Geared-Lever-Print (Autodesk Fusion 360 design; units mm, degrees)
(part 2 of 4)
sketch "M5 stop reinforcement bolt" plane through (-36.1, 0, 0) normal (1, 0, 0) x axis (0, 0, -1)
  circle C1 centre (-79.6754, -33.9652) radius 2.7
extrude "Extrude12" cut sketch "M5 stop reinforcement bolt" along normal blind 27.2
work_plane "WorkPlane13" AlongDistance -15.4 ExtraOffset 0
sketch "M5 captive stop nut" plane through (-15.4, 0, 0) normal (1, 0, 0) x axis (0, 0, -1)
  line L1 (-83.8754, -31.5403) -> (-79.6754, -29.1154)
  line L2 (-83.8754, -36.39) -> (-83.8754, -31.5403)
  line L3 (-79.6754, -38.8149) -> (-83.8754, -36.39)
  line L4 (-75.4754, -36.39) -> (-79.6754, -38.8149)
  line L5 (-75.4754, -31.5403) -> (-75.4754, -36.39)
  line L6 (-79.6754, -29.1154) -> (-75.4754, -31.5403)
extrude "Extrude13" cut sketch "M5 captive stop nut" along normal blind 6.5
work_plane "WorkPlane14" AlongDistance -36 ExtraOffset 0
sketch "Broad stop support ear (1)" plane through (-36, 0, 0) normal (1, 0, 0) x axis (0, 0, -1)
  line L1 (-60, 44) -> (-60, 20)
  line L2 (-90, 44) -> (-60, 44)
  line L3 (-90, 20) -> (-90, 44)
  line L4 (-60, 20) -> (-90, 20)
extrude "Extrude14" add sketch "Broad stop support ear (1)" along normal blind 12
work_plane "WorkPlane15" AlongDistance -24 ExtraOffset 0
sketch "Integrated steel-core end stop (1)" plane through (-24, 0, 0) normal (1, 0, 0) x axis (0, 0, -1)
  circle C1 centre (-79.6754, 33.9652) radius 6
extrude "Extrude15" add sketch "Integrated steel-core end stop (1)" along normal blind 15
work_plane "WorkPlane16" AlongDistance -36.1 ExtraOffset 0
sketch "M5 stop reinforcement bolt (1)" plane through (-36.1, 0, 0) normal (1, 0, 0) x axis (0, 0, -1)
  circle C1 centre (-79.6754, 33.9652) radius 2.7
extrude "Extrude16" cut sketch "M5 stop reinforcement bolt (1)" along normal blind 27.2
work_plane "WorkPlane17" AlongDistance -15.4 ExtraOffset 0
sketch "M5 captive stop nut (1)" plane through (-15.4, 0, 0) normal (1, 0, 0) x axis (0, 0, -1)
  line L1 (-83.8754, 36.39) -> (-79.6754, 38.8149)
  line L2 (-83.8754, 31.5403) -> (-83.8754, 36.39)
  line L3 (-79.6754, 29.1154) -> (-83.8754, 31.5403)
  line L4 (-75.4754, 31.5403) -> (-79.6754, 29.1154)
  line L5 (-75.4754, 36.39) -> (-75.4754, 31.5403)
  line L6 (-79.6754, 38.8149) -> (-75.4754, 36.39)
extrude "Extrude17" cut sketch "M5 captive stop nut (1)" along normal blind 6.5
work_plane "WorkPlane13" AlongDistance -24 ExtraOffset 0
sketch "Restore shaft socket through stop-lug root" plane through (-24, 0, 0) normal (1, 0, 0) x axis (0, 0, -1)
  line L1 (-69.6247, 6.65) -> (-60.3753, 6.65)
  arc A1 centre (-65, 0) radius 8.1 clockwise from (-60.3753, 6.65) to (-69.6247, 6.65)
extrude "Extrude13" cut sketch "Restore shaft socket through stop-lug root" along normal blind 48
work_plane "WorkPlane10" AlongDistance -24.1 ExtraOffset 0
sketch "Cam sweep clearance through crossblock" plane through (-24.1, 0, 0) normal (1, 0, 0) x axis (0, 0, -1)
  circle C1 centre (-65, 0) radius 51
extrude "Extrude10" cut sketch "Cam sweep clearance through crossblock" along normal blind 48.2
work_plane "WorkPlane10" AlongDistance 36 ExtraOffset 0
sketch "Rigid sensor carriage support" plane through (36, 0, 0) normal (1, 0, 0) x axis (0, 0, -1)
  line L1 (-49, -18) -> (-49, -28)
  line L2 (-81, -18) -> (-49, -18)
  line L3 (-81, -28) -> (-81, -18)
  line L4 (-49, -28) -> (-81, -28)
extrude "Extrude10" add sketch "Rigid sensor carriage support" along normal blind 44
work_plane "WorkPlane11" AlongDistance -28.1 ExtraOffset 0
sketch "M3 sensor carriage heat set" plane through (0, -28.1, 0) normal (0, 1, 0) x axis (1, 0, 0)
  circle C1 centre (74, -65) radius 2
extrude "Extrude11" cut sketch "M3 sensor carriage heat set" along normal blind 6.8
work_plane "WorkPlane12" AlongDistance 36 ExtraOffset 0
sketch "Rigid sensor carriage support (1)" plane through (36, 0, 0) normal (1, 0, 0) x axis (0, 0, -1)
  line L1 (-49, 28) -> (-49, 18)
  line L2 (-81, 28) -> (-49, 28)
  line L3 (-81, 18) -> (-81, 28)
  line L4 (-49, 18) -> (-81, 18)
extrude "Extrude12" add sketch "Rigid sensor carriage support (1)" along normal blind 44
work_plane "WorkPlane13" AlongDistance 21.3 ExtraOffset 0
sketch "M3 sensor carriage heat set (1)" plane through (0, 21.3, 0) normal (0, 1, 0) x axis (1, 0, 0)
  circle C1 centre (74, -65) radius 2
extrude "Extrude13" cut sketch "M3 sensor carriage heat set (1)" along normal blind 6.8
work_plane "WorkPlane1" AlongDistance -24 ExtraOffset 0
sketch "Controlled follower end float" plane through (-24, 0, 0) normal (1, 0, 0) x axis (0, 0, -1)
  circle C1 centre (-12, -35) radius 6
extrude "Extrude1" new body sketch "Controlled follower end float" along normal blind 27.8 bodies "P21 Follower left axial spacer"
work_plane "WorkPlane2" AlongDistance -24.1 ExtraOffset 0
sketch "Pivot sleeve running clearance" plane through (-24.1, 0, 0) normal (1, 0, 0) x axis (0, 0, -1)
  circle C1 centre (-12, -35) radius 4.2
extrude "Extrude2" cut sketch "Pivot sleeve running clearance" along normal blind 28
work_plane "WorkPlane1" AlongDistance 20.2 ExtraOffset 0
sketch "Controlled follower end float" plane through (20.2, 0, 0) normal (1, 0, 0) x axis (0, 0, -1)
  circle C1 centre (-12, -35) radius 6
extrude "Extrude1" new body sketch "Controlled follower end float" along normal blind 3.8 bodies "P22 Follower right axial spacer"
work_plane "WorkPlane2" AlongDistance 20.1 ExtraOffset 0
sketch "Pivot sleeve running clearance" plane through (20.1, 0, 0) normal (1, 0, 0) x axis (0, 0, -1)
  circle C1 centre (-12, -35) radius 4.2
extrude "Extrude2" cut sketch "Pivot sleeve running clearance" along normal blind 4
work_plane "WorkPlane1" AlongDistance 3.1 ExtraOffset 0
sketch "Roller axle M3 nut" plane through (3.1, 0, 0) normal (1, 0, 0) x axis (0, 0, -1)
  line L1 (-14.75, 1.5877) -> (-12, 3.1754)
  line L2 (-14.75, -1.5877) -> (-14.75, 1.5877)
  line L3 (-12, -3.1754) -> (-14.75, -1.5877)
  line L4 (-9.25, -1.5877) -> (-12, -3.1754)
  line L5 (-9.25, 1.5877) -> (-9.25, -1.5877)
  line L6 (-12, 3.1754) -> (-9.25, 1.5877)
extrude "Extrude1" new body sketch "Roller axle M3 nut" along normal blind 2.4 bodies "HARDWARE Roller axle M3 nut"
work_plane "WorkPlane2" AlongDistance 3 ExtraOffset 0
sketch "Thread envelope" plane through (3, 0, 0) normal (1, 0, 0) x axis (0, 0, -1)
  circle C1 centre (-12, 0) radius 1.5
extrude "Extrude2" cut sketch "Thread envelope" along normal blind 2.6
work_plane "WorkPlane14" AlongDistance 23.9 ExtraOffset 0
sketch "Cam lateral service opening" plane through (23.9, 0, 0) normal (1, 0, 0) x axis (0, 0, -1)
  line L1 (-42.2047, 46.7373) -> (-43.8497, 47.5044)
  line L2 (-40.5875, 45.9133) -> (-42.2047, 46.7373)
  line L3 (-39, 45.0333) -> (-40.5875, 45.9133)
  line L4 (-37.4442, 44.0985) -> (-39, 45.0333)
  line L5 (-35.922, 43.11) -> (-37.4442, 44.0985)
  line L6 (-34.4352, 42.0689) -> (-35.922, 43.11)
  line L7 (-32.9856, 40.9766) -> (-34.4352, 42.0689)
  line L8 (-31.575, 39.8343) -> (-32.9856, 40.9766)
  line L9 (-30.2052, 38.6435) -> (-31.575, 39.8343)
  line L10 (-28.8778, 37.4057) -> (-30.2052, 38.6435)
  line L11 (-27.5943, 36.1222) -> (-28.8778, 37.4057)
  line L12 (-26.3565, 34.7948) -> (-27.5943, 36.1222)
  line L13 (-25.1657, 33.425) -> (-26.3565, 34.7948)
  line L14 (-24.0234, 32.0144) -> (-25.1657, 33.425)
  line L15 (-22.9311, 30.5648) -> (-24.0234, 32.0144)
  line L16 (-21.89, 29.078) -> (-22.9311, 30.5648)
  line L17 (-20.9015, 27.5558) -> (-21.89, 29.078)
  line L18 (-19.9667, 26) -> (-20.9015, 27.5558)
  line L19 (-19.0867, 24.4125) -> (-19.9667, 26)
  line L20 (-18.2627, 22.7953) -> (-19.0867, 24.4125)
  line L21 (-17.4956, 21.1503) -> (-18.2627, 22.7953)
  line L22 (-16.7864, 19.4795) -> (-17.4956, 21.1503)
  line L23 (-16.136, 17.785) -> (-16.7864, 19.4795)
  line L24 (-15.5451, 16.0689) -> (-16.136, 17.785)
  line L25 (-15.0144, 14.3331) -> (-15.5451, 16.0689)
  line L26 (-14.5446, 12.5799) -> (-15.0144, 14.3331)
  line L27 (-14.1363, 10.8114) -> (-14.5446, 12.5799)
  line L28 (-13.79, 9.0297) -> (-14.1363, 10.8114)
  line L29 (-13.5061, 7.237) -> (-13.79, 9.0297)
  line L30 (-13.2849, 5.4355) -> (-13.5061, 7.237)
  line L31 (-13.1267, 3.6273) -> (-13.2849, 5.4355)
  line L32 (-13.0317, 1.8148) -> (-13.1267, 3.6273)
  line L33 (-13, 0) -> (-13.0317, 1.8148)
  line L34 (-13.0317, -1.8148) -> (-13, 0)
  line L35 (-13.1267, -3.6273) -> (-13.0317, -1.8148)
  line L36 (-13.2849, -5.4355) -> (-13.1267, -3.6273)
  line L37 (-13.5061, -7.237) -> (-13.2849, -5.4355)
  line L38 (-13.79, -9.0297) -> (-13.5061, -7.237)
  line L39 (-14.1363, -10.8114) -> (-13.79, -9.0297)
  line L40 (-14.5446, -12.5799) -> (-14.1363, -10.8114)
  line L41 (-15.0144, -14.3331) -> (-14.5446, -12.5799)
  line L42 (-15.5451, -16.0689) -> (-15.0144, -14.3331)
  line L43 (-16.136, -17.785) -> (-15.5451, -16.0689)
  line L44 (-16.7864, -19.4795) -> (-16.136, -17.785)
  line L45 (-17.4956, -21.1503) -> (-16.7864, -19.4795)
  line L46 (-18.2627, -22.7953) -> (-17.4956, -21.1503)
  line L47 (-19.0867, -24.4125) -> (-18.2627, -22.7953)
  line L48 (-19.9667, -26) -> (-19.0867, -24.4125)
  line L49 (-20.9015, -27.5558) -> (-19.9667, -26)
  line L50 (-21.89, -29.078) -> (-20.9015, -27.5558)
  line L51 (-22.9311, -30.5648) -> (-21.89, -29.078)
  line L52 (-24.0234, -32.0144) -> (-22.9311, -30.5648)
  line L53 (-25.1657, -33.425) -> (-24.0234, -32.0144)
  line L54 (-26.3565, -34.7948) -> (-25.1657, -33.425)
  line L55 (-27.5943, -36.1222) -> (-26.3565, -34.7948)
  line L56 (-28.8778, -37.4057) -> (-27.5943, -36.1222)
  line L57 (-30.2052, -38.6435) -> (-28.8778, -37.4057)
  line L58 (-31.575, -39.8343) -> (-30.2052, -38.6435)
  line L59 (-32.9856, -40.9766) -> (-31.575, -39.8343)
  line L60 (-34.4352, -42.0689) -> (-32.9856, -40.9766)
  line L61 (-35.922, -43.11) -> (-34.4352, -42.0689)
  line L62 (-37.4442, -44.0985) -> (-35.922, -43.11)
  line L63 (-39, -45.0333) -> (-37.4442, -44.0985)
  line L64 (-40.5875, -45.9133) -> (-39, -45.0333)
  line L65 (-42.2047, -46.7373) -> (-40.5875, -45.9133)
  line L66 (-43.8497, -47.5044) -> (-42.2047, -46.7373)
  line L67 (-54.4248, -23.7522) -> (-43.8497, -47.5044)
  line L68 (-53.6024, -23.3686) -> (-54.4248, -23.7522)
  line L69 (-52.7937, -22.9566) -> (-53.6024, -23.3686)
  line L70 (-52, -22.5167) -> (-52.7937, -22.9566)
  line L71 (-51.2221, -22.0493) -> (-52, -22.5167)
  line L72 (-50.461, -21.555) -> (-51.2221, -22.0493)
  line L73 (-49.7176, -21.0344) -> (-50.461, -21.555)
  line L74 (-48.9928, -20.4883) -> (-49.7176, -21.0344)
  line L75 (-48.2875, -19.9172) -> (-48.9928, -20.4883)
  line L76 (-47.6026, -19.3218) -> (-48.2875, -19.9172)
  line L77 (-46.9389, -18.7028) -> (-47.6026, -19.3218)
  line L78 (-46.2972, -18.0611) -> (-46.9389, -18.7028)
  line L79 (-45.6782, -17.3974) -> (-46.2972, -18.0611)
  line L80 (-45.0828, -16.7125) -> (-45.6782, -17.3974)
  line L81 (-44.5117, -16.0072) -> (-45.0828, -16.7125)
  line L82 (-43.9656, -15.2824) -> (-44.5117, -16.0072)
  line L83 (-43.445, -14.539) -> (-43.9656, -15.2824)
  line L84 (-42.9507, -13.7779) -> (-43.445, -14.539)
  line L85 (-42.4833, -13) -> (-42.9507, -13.7779)
  line L86 (-42.0434, -12.2063) -> (-42.4833, -13)
  line L87 (-41.6314, -11.3976) -> (-42.0434, -12.2063)
  line L88 (-41.2478, -10.5752) -> (-41.6314, -11.3976)
  line L89 (-40.8932, -9.7398) -> (-41.2478, -10.5752)
  line L90 (-40.568, -8.8925) -> (-40.8932, -9.7398)
  line L91 (-40.2725, -8.0344) -> (-40.568, -8.8925)
  line L92 (-40.0072, -7.1666) -> (-40.2725, -8.0344)
  line L93 (-39.7723, -6.29) -> (-40.0072, -7.1666)
  line L94 (-39.5682, -5.4057) -> (-39.7723, -6.29)
  line L95 (-39.395, -4.5149) -> (-39.5682, -5.4057)
  line L96 (-39.253, -3.6185) -> (-39.395, -4.5149)
  line L97 (-39.1424, -2.7177) -> (-39.253, -3.6185)
  line L98 (-39.0633, -1.8137) -> (-39.1424, -2.7177)
  line L99 (-39.0158, -0.9074) -> (-39.0633, -1.8137)
  line L100 (-39, 0) -> (-39.0158, -0.9074)
  line L101 (-39.0158, 0.9074) -> (-39, 0)
  line L102 (-39.0633, 1.8137) -> (-39.0158, 0.9074)
  line L103 (-39.1424, 2.7177) -> (-39.0633, 1.8137)
  line L104 (-39.253, 3.6185) -> (-39.1424, 2.7177)
  line L105 (-39.395, 4.5149) -> (-39.253, 3.6185)
  line L106 (-39.5682, 5.4057) -> (-39.395, 4.5149)
  line L107 (-39.7723, 6.29) -> (-39.5682, 5.4057)
  line L108 (-40.0072, 7.1666) -> (-39.7723, 6.29)
  line L109 (-40.2725, 8.0344) -> (-40.0072, 7.1666)
  line L110 (-40.568, 8.8925) -> (-40.2725, 8.0344)
  line L111 (-40.8932, 9.7398) -> (-40.568, 8.8925)
  line L112 (-41.2478, 10.5752) -> (-40.8932, 9.7398)
  line L113 (-41.6314, 11.3976) -> (-41.2478, 10.5752)
  line L114 (-42.0434, 12.2063) -> (-41.6314, 11.3976)
  line L115 (-42.4833, 13) -> (-42.0434, 12.2063)
  line L116 (-42.9507, 13.7779) -> (-42.4833, 13)
  line L117 (-43.445, 14.539) -> (-42.9507, 13.7779)
  line L118 (-43.9656, 15.2824) -> (-43.445, 14.539)
  line L119 (-44.5117, 16.0072) -> (-43.9656, 15.2824)
  line L120 (-45.0828, 16.7125) -> (-44.5117, 16.0072)
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extrude "Extrude14" cut sketch "Cam lateral service opening" along normal blind 12.2
work_plane "WorkPlane15" AlongDistance 36 ExtraOffset 0
sketch "Clear service path beneath sensor rails" plane through (36, 0, 0) normal (1, 0, 0) x axis (0, 0, -1)
  line L1 (-48.9, -18) -> (-48.9, -28)
  line L2 (-56, -18) -> (-48.9, -18)
  line L3 (-56, -28) -> (-56, -18)
  line L4 (-48.9, -28) -> (-56, -28)
extrude "Extrude15" cut sketch "Clear service path beneath sensor rails" along normal blind 44.1
work_plane "WorkPlane16" AlongDistance 36 ExtraOffset 0
sketch "Clear service path beneath sensor rails (1)" plane through (36, 0, 0) normal (1, 0, 0) x axis (0, 0, -1)
  line L1 (-48.9, 28) -> (-48.9, 18)
  line L2 (-56, 28) -> (-48.9, 28)
  line L3 (-56, 18) -> (-56, 28)
  line L4 (-48.9, 18) -> (-56, 18)
extrude "Extrude16" cut sketch "Clear service path beneath sensor rails (1)" along normal blind 44.1
work_plane "WorkPlane11" AlongDistance -24 ExtraOffset 0
sketch "Raise mount clear of rail bolt axes" plane through (-24, 0, 0) normal (1, 0, 0) x axis (0, 0, -1)
  line L1 (-52, -44) -> (-52, -66)
  line L2 (-57, -44) -> (-52, -44)
  line L3 (-57, -66) -> (-57, -44)
  line L4 (-52, -66) -> (-57, -66)
extrude "Extrude11" add sketch "Raise mount clear of rail bolt axes" along normal blind 48
work_plane "WorkPlane12" AlongDistance -24 ExtraOffset 0
sketch "Close old block mounting hole" plane through (-24, 0, 0) normal (1, 0, 0) x axis (0, 0, -1)
  circle C1 centre (-44, -59) radius 2.01
extrude "Extrude12" add sketch "Close old block mounting hole" along normal blind 8.7
work_plane "WorkPlane13" AlongDistance -24.1 ExtraOffset 0
sketch "Raised M3 block insert" plane through (-24.1, 0, 0) normal (1, 0, 0) x axis (0, 0, -1)
  circle C1 centre (-52, -59) radius 2
extrude "Extrude13" cut sketch "Raised M3 block insert" along normal blind 8.9
work_plane "WorkPlane14" AlongDistance 15.3 ExtraOffset 0
sketch "Close old block mounting hole (1)" plane through (15.3, 0, 0) normal (1, 0, 0) x axis (0, 0, -1)
  circle C1 centre (-44, -59) radius 2.01
extrude "Extrude14" add sketch "Close old block mounting hole (1)" along normal blind 8.7
work_plane "WorkPlane15" AlongDistance 15.2 ExtraOffset 0
sketch "Raised M3 block insert (1)" plane through (15.2, 0, 0) normal (1, 0, 0) x axis (0, 0, -1)
  circle C1 centre (-52, -59) radius 2
extrude "Extrude15" cut sketch "Raised M3 block insert (1)" along normal blind 8.9
work_plane "WorkPlane18" AlongDistance -36 ExtraOffset 0
sketch "Close old plate mounting hole" plane through (-36, 0, 0) normal (1, 0, 0) x axis (0, 0, -1)
  circle C1 centre (-44, -59) radius 1.71
extrude "Extrude18" add sketch "Close old plate mounting hole" along normal blind 12
work_plane "WorkPlane19" AlongDistance -36.1 ExtraOffset 0
sketch "Raised M3 block fastener" plane through (-36.1, 0, 0) normal (1, 0, 0) x axis (0, 0, -1)
  circle C1 centre (-52, -59) radius 1.7
extrude "Extrude19" cut sketch "Raised M3 block fastener" along normal blind 12.2
work_plane "WorkPlane17" AlongDistance 24 ExtraOffset 0
sketch "Close old plate mounting hole" plane through (24, 0, 0) normal (1, 0, 0) x axis (0, 0, -1)
  circle C1 centre (-44, -59) radius 1.71
extrude "Extrude17" add sketch "Close old plate mounting hole" along normal blind 12
work_plane "WorkPlane18" AlongDistance 23.9 ExtraOffset 0
sketch "Raised M3 block fastener" plane through (23.9, 0, 0) normal (1, 0, 0) x axis (0, 0, -1)
  circle C1 centre (-52, -59) radius 1.7
extrude "Extrude18" cut sketch "Raised M3 block fastener" along normal blind 12.2
work_plane "WorkPlane16" AlongDistance -24 ExtraOffset 0
sketch "Close old block mounting hole (2)" plane through (-24, 0, 0) normal (1, 0, 0) x axis (0, 0, -1)
  circle C1 centre (-44, -51) radius 2.01
extrude "Extrude16" add sketch "Close old block mounting hole (2)" along normal blind 8.7
work_plane "WorkPlane17" AlongDistance -24.1 ExtraOffset 0
sketch "Raised M3 block insert (2)" plane through (-24.1, 0, 0) normal (1, 0, 0) x axis (0, 0, -1)
  circle C1 centre (-52, -51) radius 2
extrude "Extrude17" cut sketch "Raised M3 block insert (2)" along normal blind 8.9
work_plane "WorkPlane18" AlongDistance 15.3 ExtraOffset 0
sketch "Close old block mounting hole (3)" plane through (15.3, 0, 0) normal (1, 0, 0) x axis (0, 0, -1)
  circle C1 centre (-44, -51) radius 2.01
extrude "Extrude18" add sketch "Close old block mounting hole (3)" along normal blind 8.7
work_plane "WorkPlane19" AlongDistance 15.2 ExtraOffset 0
sketch "Raised M3 block insert (3)" plane through (15.2, 0, 0) normal (1, 0, 0) x axis (0, 0, -1)
  circle C1 centre (-52, -51) radius 2
extrude "Extrude19" cut sketch "Raised M3 block insert (3)" along normal blind 8.9
work_plane "WorkPlane20" AlongDistance -36 ExtraOffset 0
sketch "Close old plate mounting hole (1)" plane through (-36, 0, 0) normal (1, 0, 0) x axis (0, 0, -1)
  circle C1 centre (-44, -51) radius 1.71
extrude "Extrude20" add sketch "Close old plate mounting hole (1)" along normal blind 12
work_plane "WorkPlane21" AlongDistance -36.1 ExtraOffset 0
sketch "Raised M3 block fastener (1)" plane through (-36.1, 0, 0) normal (1, 0, 0) x axis (0, 0, -1)
  circle C1 centre (-52, -51) radius 1.7
extrude "Extrude21" cut sketch "Raised M3 block fastener (1)" along normal blind 12.2
work_plane "WorkPlane19" AlongDistance 24 ExtraOffset 0
sketch "Close old plate mounting hole (1)" plane through (24, 0, 0) normal (1, 0, 0) x axis (0, 0, -1)
  circle C1 centre (-44, -51) radius 1.71
extrude "Extrude19" add sketch "Close old plate mounting hole (1)" along normal blind 12
work_plane "WorkPlane20" AlongDistance 23.9 ExtraOffset 0
sketch "Raised M3 block fastener (1)" plane through (23.9, 0, 0) normal (1, 0, 0) x axis (0, 0, -1)
  circle C1 centre (-52, -51) radius 1.7
extrude "Extrude20" cut sketch "Raised M3 block fastener (1)" along normal blind 12.2
work_plane "WorkPlane20" AlongDistance 51.9 ExtraOffset 0
sketch "Continue adjuster bore" plane through (0, 0, 51.9) normal (0, 0, 1) x axis (1, 0, 0)
  circle C1 centre (12, -55) radius 2.2
extrude "Extrude20" cut sketch "Continue adjuster bore" along normal blind 5.2
work_plane "WorkPlane21" AlongDistance 51.9 ExtraOffset 0
sketch "Continue guide bore" plane through (0, 0, 51.9) normal (0, 0, 1) x axis (1, 0, 0)
  circle C1 centre (5, -55) radius 1.7
extrude "Extrude21" cut sketch "Continue guide bore" along normal blind 5.2
work_plane "WorkPlane22" AlongDistance 51.9 ExtraOffset 0
sketch "Continue guide bore (1)" plane through (0, 0, 51.9) normal (0, 0, 1) x axis (1, 0, 0)
  circle C1 centre (19, -55) radius 1.7
extrude "Extrude22" cut sketch "Continue guide bore (1)" along normal blind 5.2
work_plane "WorkPlane23" AlongDistance -24.1 ExtraOffset 0
sketch "Preserve cam sweep clearance" plane through (-24.1, 0, 0) normal (1, 0, 0) x axis (0, 0, -1)
  circle C1 centre (-65, 0) radius 51
extrude "Extrude23" cut sketch "Preserve cam sweep clearance" along normal blind 48.2
work_plane "WorkPlane1" AlongDistance -23.85 ExtraOffset 0
sketch "Controlled rotor axial clearance" plane through (-23.85, 0, 0) normal (1, 0, 0) x axis (0, 0, -1)
  circle C1 centre (-65, 0) radius 10
extrude "Extrude1" new body sketch "Controlled rotor axial clearance" along normal blind 16.85 bodies "P23 Left rotor thrust spacer"
work_plane "WorkPlane2" AlongDistance -23.95 ExtraOffset 0
sketch "Free spacer bore" plane through (-23.95, 0, 0) normal (1, 0, 0) x axis (0, 0, -1)
  circle C1 centre (-65, 0) radius 8.2
extrude "Extrude2" cut sketch "Free spacer bore" along normal blind 17.05
work_plane "WorkPlane1" AlongDistance 7 ExtraOffset 0
sketch "Controlled rotor axial clearance" plane through (7, 0, 0) normal (1, 0, 0) x axis (0, 0, -1)
  circle C1 centre (-65, 0) radius 10
extrude "Extrude1" new body sketch "Controlled rotor axial clearance" along normal blind 16.85 bodies "P24 Right rotor thrust spacer"
work_plane "WorkPlane2" AlongDistance 6.9 ExtraOffset 0
sketch "Free spacer bore" plane through (6.9, 0, 0) normal (1, 0, 0) x axis (0, 0, -1)
  circle C1 centre (-65, 0) radius 8.2
extrude "Extrude2" cut sketch "Free spacer bore" along normal blind 17.05
work_plane "WorkPlane22" AlongDistance -76 ExtraOffset 0
sketch "Restore rail bolt clearance after hole filling" plane through (0, -76, 0) normal (0, 1, 0) x axis (1, 0, 0)
  circle C1 centre (-30, -45) radius 2.7
extrude "Extrude22" cut sketch "Restore rail bolt clearance after hole filling" along normal blind 22
work_plane "WorkPlane23" AlongDistance 54 ExtraOffset 0
sketch "Restore rail bolt clearance after hole filling (1)" plane through (0, 54, 0) normal (0, 1, 0) x axis (1, 0, 0)
  circle C1 centre (-30, -45) radius 2.7
work_plane "WorkPlane24" AlongDistance -55 ExtraOffset 0
sketch "Restore rail head access after hole filling" plane through (0, -55, 0) normal (0, 1, 0) x axis (1, 0, 0)
  circle C1 centre (-30, -45) radius 5.3
extrude "Extrude24" cut sketch "Restore rail head access after hole filling" along normal blind 12
work_plane "WorkPlane25" AlongDistance 43 ExtraOffset 0
sketch "Restore rail head access after hole filling (1)" plane through (0, 43, 0) normal (0, 1, 0) x axis (1, 0, 0)
  circle C1 centre (-30, -45) radius 5.3
work_plane "WorkPlane21" AlongDistance -76 ExtraOffset 0
sketch "Restore rail bolt clearance after hole filling" plane through (0, -76, 0) normal (0, 1, 0) x axis (1, 0, 0)
  circle C1 centre (30, -45) radius 2.7
extrude "Extrude21" cut sketch "Restore rail bolt clearance after hole filling" along normal blind 22
work_plane "WorkPlane22" AlongDistance 54 ExtraOffset 0
sketch "Restore rail bolt clearance after hole filling (1)" plane through (0, 54, 0) normal (0, 1, 0) x axis (1, 0, 0)
  circle C1 centre (30, -45) radius 2.7
work_plane "WorkPlane23" AlongDistance -55 ExtraOffset 0
sketch "Restore rail head access after hole filling" plane through (0, -55, 0) normal (0, 1, 0) x axis (1, 0, 0)
  circle C1 centre (30, -45) radius 5.3
extrude "Extrude23" cut sketch "Restore rail head access after hole filling" along normal blind 12
work_plane "WorkPlane24" AlongDistance 43 ExtraOffset 0
sketch "Restore rail head access after hole filling (1)" plane through (0, 43, 0) normal (0, 1, 0) x axis (1, 0, 0)
  circle C1 centre (30, -45) radius 5.3
work_plane "WorkPlane14" AlongDistance -18.1 ExtraOffset 0
sketch "Stop lug clearance for concentric thrust spacer" plane through (-18.1, 0, 0) normal (1, 0, 0) x axis (0, 0, -1)
  circle C1 centre (-65, 0) radius 10.2
extrude "Extrude14" cut sketch "Stop lug clearance for concentric thrust spacer" along normal blind 11
work_plane "WorkPlane15" AlongDistance -18.1 ExtraOffset 0
sketch "Complete stop lug relief to rotor face" plane through (-18.1, 0, 0) normal (1, 0, 0) x axis (0, 0, -1)
  circle C1 centre (-65, 0) radius 10.2
extrude "Extrude15" cut sketch "Complete stop lug relief to rotor face" along normal blind 11.1
ground "Pin2"
ground "Pin3"
ground "Pin4"
ground "Pin5"
ground "Pin6"
ground "Pin11"
ground "Pin12"
ground "Pin48"
ground "Pin49"
work_plane "WorkPlane24" AlongDistance -24 ExtraOffset 0
sketch "Extra roof over relocated heat-set inserts" plane through (-24, 0, 0) normal (1, 0, 0) x axis (0, 0, -1)
  line L1 (-57, -44) -> (-57, -66)
  line L2 (-59, -44) -> (-57, -44)
  line L3 (-59, -66) -> (-59, -44)
  line L4 (-57, -66) -> (-59, -66)
extrude "Extrude24" add sketch "Extra roof over relocated heat-set inserts" along normal blind 48
work_plane "WorkPlane25" AlongDistance -24 ExtraOffset 0
sketch "Fill former insert location" plane through (-24, 0, 0) normal (1, 0, 0) x axis (0, 0, -1)
  circle C1 centre (-52, -59) radius 2.01
extrude "Extrude25" add sketch "Fill former insert location" along normal blind 8.7
work_plane "WorkPlane26" AlongDistance 15.3 ExtraOffset 0
sketch "Fill former insert location (1)" plane through (15.3, 0, 0) normal (1, 0, 0) x axis (0, 0, -1)
  circle C1 centre (-52, -59) radius 2.01
extrude "Extrude26" add sketch "Fill former insert location (1)" along normal blind 8.7
work_plane "WorkPlane26" AlongDistance -36 ExtraOffset 0
sketch "Fill former plate mounting hole" plane through (-36, 0, 0) normal (1, 0, 0) x axis (0, 0, -1)
  circle C1 centre (-52, -59) radius 1.71
extrude "Extrude26" add sketch "Fill former plate mounting hole" along normal blind 12
work_plane "WorkPlane25" AlongDistance 24 ExtraOffset 0
sketch "Fill former plate mounting hole" plane through (24, 0, 0) normal (1, 0, 0) x axis (0, 0, -1)
  circle C1 centre (-52, -59) radius 1.71
extrude "Extrude25" add sketch "Fill former plate mounting hole" along normal blind 12
work_plane "WorkPlane27" AlongDistance -24 ExtraOffset 0
sketch "Fill former insert location (2)" plane through (-24, 0, 0) normal (1, 0, 0) x axis (0, 0, -1)
  circle C1 centre (-52, -51) radius 2.01
extrude "Extrude27" add sketch "Fill former insert location (2)" along normal blind 8.7
work_plane "WorkPlane28" AlongDistance 15.3 ExtraOffset 0
sketch "Fill former insert location (3)" plane through (15.3, 0, 0) normal (1, 0, 0) x axis (0, 0, -1)
  circle C1 centre (-52, -51) radius 2.01
extrude "Extrude28" add sketch "Fill former insert location (3)" along normal blind 8.7
work_plane "WorkPlane27" AlongDistance -36 ExtraOffset 0
sketch "Fill former plate mounting hole (1)" plane through (-36, 0, 0) normal (1, 0, 0) x axis (0, 0, -1)
  circle C1 centre (-52, -51) radius 1.71
extrude "Extrude27" add sketch "Fill former plate mounting hole (1)" along normal blind 12
work_plane "WorkPlane26" AlongDistance 24 ExtraOffset 0
sketch "Fill former plate mounting hole (1)" plane through (24, 0, 0) normal (1, 0, 0) x axis (0, 0, -1)
  circle C1 centre (-52, -51) radius 1.71
extrude "Extrude26" add sketch "Fill former plate mounting hole (1)" along normal blind 12
work_plane "WorkPlane29" AlongDistance -24.1 ExtraOffset 0
sketch "Relocated insert with cam-side retaining wall" plane through (-24.1, 0, 0) normal (1, 0, 0) x axis (0, 0, -1)
  circle C1 centre (-53.5, -62) radius 2
extrude "Extrude29" cut sketch "Relocated insert with cam-side retaining wall" along normal blind 8.9
work_plane "WorkPlane30" AlongDistance 15.3 ExtraOffset 0
sketch "Relocated insert with cam-side retaining wall (1)" plane through (15.3, 0, 0) normal (1, 0, 0) x axis (0, 0, -1)
  circle C1 centre (-53.5, -62) radius 2
extrude "Extrude30" cut sketch "Relocated insert with cam-side retaining wall (1)" along normal blind 8.9
work_plane "WorkPlane28" AlongDistance -36.1 ExtraOffset 0
sketch "Relocated mount above rail counterbore" plane through (-36.1, 0, 0) normal (1, 0, 0) x axis (0, 0, -1)
  circle C1 centre (-53.5, -62) radius 1.7
extrude "Extrude28" cut sketch "Relocated mount above rail counterbore" along normal blind 12.2
work_plane "WorkPlane27" AlongDistance 23.9 ExtraOffset 0
sketch "Relocated mount above rail counterbore" plane through (23.9, 0, 0) normal (1, 0, 0) x axis (0, 0, -1)
  circle C1 centre (-53.5, -62) radius 1.7
extrude "Extrude27" cut sketch "Relocated mount above rail counterbore" along normal blind 12.2
work_plane "WorkPlane31" AlongDistance -24.1 ExtraOffset 0
sketch "Relocated insert with cam-side retaining wall (2)" plane through (-24.1, 0, 0) normal (1, 0, 0) x axis (0, 0, -1)
  circle C1 centre (-53.5, -54) radius 2
extrude "Extrude31" cut sketch "Relocated insert with cam-side retaining wall (2)" along normal blind 8.9
work_plane "WorkPlane32" AlongDistance 15.3 ExtraOffset 0
sketch "Relocated insert with cam-side retaining wall (3)" plane through (15.3, 0, 0) normal (1, 0, 0) x axis (0, 0, -1)
  circle C1 centre (-53.5, -54) radius 2
extrude "Extrude32" cut sketch "Relocated insert with cam-side retaining wall (3)" along normal blind 8.9
work_plane "WorkPlane29" AlongDistance -36.1 ExtraOffset 0
sketch "Relocated mount above rail counterbore (1)" plane through (-36.1, 0, 0) normal (1, 0, 0) x axis (0, 0, -1)
  circle C1 centre (-53.5, -54) radius 1.7
extrude "Extrude29" cut sketch "Relocated mount above rail counterbore (1)" along normal blind 12.2
work_plane "WorkPlane28" AlongDistance 23.9 ExtraOffset 0
sketch "Relocated mount above rail counterbore (1)" plane through (23.9, 0, 0) normal (1, 0, 0) x axis (0, 0, -1)
  circle C1 centre (-53.5, -54) radius 1.7
extrude "Extrude28" cut sketch "Relocated mount above rail counterbore (1)" along normal blind 12.2
work_plane "WorkPlane33" AlongDistance 51.9 ExtraOffset 0
sketch "Continue adjuster bore through roof" plane through (0, 0, 51.9) normal (0, 0, 1) x axis (1, 0, 0)
  circle C1 centre (12, -55) radius 2.2
extrude "Extrude33" cut sketch "Continue adjuster bore through roof" along normal blind 7.2
work_plane "WorkPlane34" AlongDistance 51.9 ExtraOffset 0
sketch "Continue guide bore through roof" plane through (0, 0, 51.9) normal (0, 0, 1) x axis (1, 0, 0)
  circle C1 centre (5, -55) radius 1.7
extrude "Extrude34" cut sketch "Continue guide bore through roof" along normal blind 7.2
work_plane "WorkPlane35" AlongDistance 51.9 ExtraOffset 0
sketch "Continue guide bore through roof (1)" plane through (0, 0, 51.9) normal (0, 0, 1) x axis (1, 0, 0)
  circle C1 centre (19, -55) radius 1.7
extrude "Extrude35" cut sketch "Continue guide bore through roof (1)" along normal blind 7.2
work_plane "WorkPlane36" AlongDistance -24.1 ExtraOffset 0
sketch "Restore cam envelope after pocket repair" plane through (-24.1, 0, 0) normal (1, 0, 0) x axis (0, 0, -1)
  circle C1 centre (-65, 0) radius 51
extrude "Extrude36" cut sketch "Restore cam envelope after pocket repair" along normal blind 48.2
work_plane "WorkPlane30" AlongDistance -76 ExtraOffset 0
sketch "Preserve rail shank passage" plane through (0, -76, 0) normal (0, 1, 0) x axis (1, 0, 0)
  circle C1 centre (-30, -45) radius 2.7
work_plane "WorkPlane31" AlongDistance 54 ExtraOffset 0
sketch "Preserve rail shank passage (1)" plane through (0, 54, 0) normal (0, 1, 0) x axis (1, 0, 0)
  circle C1 centre (-30, -45) radius 2.7
work_plane "WorkPlane32" AlongDistance -55 ExtraOffset 0
sketch "Preserve rail head passage" plane through (0, -55, 0) normal (0, 1, 0) x axis (1, 0, 0)
  circle C1 centre (-30, -45) radius 5.3
extrude "Extrude32" cut sketch "Preserve rail head passage" along normal blind 12
work_plane "WorkPlane33" AlongDistance 43 ExtraOffset 0
sketch "Preserve rail head passage (1)" plane through (0, 43, 0) normal (0, 1, 0) x axis (1, 0, 0)
  circle C1 centre (-30, -45) radius 5.3
work_plane "WorkPlane29" AlongDistance -76 ExtraOffset 0
sketch "Preserve rail shank passage" plane through (0, -76, 0) normal (0, 1, 0) x axis (1, 0, 0)
  circle C1 centre (30, -45) radius 2.7
work_plane "WorkPlane30" AlongDistance 54 ExtraOffset 0
sketch "Preserve rail shank passage (1)" plane through (0, 54, 0) normal (0, 1, 0) x axis (1, 0, 0)
  circle C1 centre (30, -45) radius 2.7
work_plane "WorkPlane31" AlongDistance -55 ExtraOffset 0
sketch "Preserve rail head passage" plane through (0, -55, 0) normal (0, 1, 0) x axis (1, 0, 0)
  circle C1 centre (30, -45) radius 5.3
extrude "Extrude31" cut sketch "Preserve rail head passage" along normal blind 12
work_plane "WorkPlane32" AlongDistance 43 ExtraOffset 0
sketch "Preserve rail head passage (1)" plane through (0, 43, 0) normal (0, 1, 0) x axis (1, 0, 0)
  circle C1 centre (30, -45) radius 5.3
work_plane "WorkPlane16" AlongDistance -5 ExtraOffset 0
sketch "Flat washer seat for sensor-drive shaft clamp" plane through (-5, 0, 0) normal (1, 0, 0) x axis (0, 0, -1)
  line L1 (-60, 22) -> (-60, 20)
  line L2 (-70, 22) -> (-60, 22)
  line L3 (-70, 20) -> (-70, 22)
  line L4 (-60, 20) -> (-70, 20)
extrude "Extrude16" add sketch "Flat washer seat for sensor-drive shaft clamp" along normal blind 10
work_plane "WorkPlane17" AlongDistance 6.4 ExtraOffset 0
sketch "Radial screw onto printed shaft D flat" plane through (0, 6.4, 0) normal (0, 1, 0) x axis (1, 0, 0)
  circle C1 centre (0, -65) radius 1.7
extrude "Extrude17" cut sketch "Radial screw onto printed shaft D flat" along normal blind 15.7
work_plane "WorkPlane18" AlongDistance 15.2 ExtraOffset 0
sketch "M3 heatset pocket for rotor clamp" plane through (0, 15.2, 0) normal (0, 1, 0) x axis (1, 0, 0)
  circle C1 centre (0, -65) radius 2
extrude "Extrude18" cut sketch "M3 heatset pocket for rotor clamp" along normal blind 6.9
work_plane "WorkPlane37" AlongDistance -24 ExtraOffset 0
sketch "Extend reaction block into free rail bay" plane through (-24, 0, 0) normal (1, 0, 0) x axis (0, 0, -1)
  line L1 (-38, -66) -> (-38, -74)
  line L2 (-59, -66) -> (-38, -66)
  line L3 (-59, -74) -> (-59, -66)
  line L4 (-38, -74) -> (-59, -74)
extrude "Extrude37" add sketch "Extend reaction block into free rail bay" along normal blind 48
work_plane "WorkPlane38" AlongDistance -24 ExtraOffset 0
sketch "Close mounting bore that crossed cup guide" plane through (-24, 0, 0) normal (1, 0, 0) x axis (0, 0, -1)
  circle C1 centre (-53.5, -54) radius 2.01
extrude "Extrude38" add sketch "Close mounting bore that crossed cup guide" along normal blind 8.7
work_plane "WorkPlane39" AlongDistance -24.1 ExtraOffset 0
sketch "Outer mounting row clear of guide" plane through (-24.1, 0, 0) normal (1, 0, 0) x axis (0, 0, -1)
  circle C1 centre (-53.5, -70) radius 2
extrude "Extrude39" cut sketch "Outer mounting row clear of guide" along normal blind 8.9
work_plane "WorkPlane40" AlongDistance 15.3 ExtraOffset 0
sketch "Close mounting bore that crossed cup guide (1)" plane through (15.3, 0, 0) normal (1, 0, 0) x axis (0, 0, -1)
  circle C1 centre (-53.5, -54) radius 2.01
extrude "Extrude40" add sketch "Close mounting bore that crossed cup guide (1)" along normal blind 8.7
work_plane "WorkPlane41" AlongDistance 15.2 ExtraOffset 0
sketch "Outer mounting row clear of guide (1)" plane through (15.2, 0, 0) normal (1, 0, 0) x axis (0, 0, -1)
  circle C1 centre (-53.5, -70) radius 2
extrude "Extrude41" cut sketch "Outer mounting row clear of guide (1)" along normal blind 8.9
work_plane "WorkPlane34" AlongDistance -36 ExtraOffset 0
sketch "Close former inner mounting hole" plane through (-36, 0, 0) normal (1, 0, 0) x axis (0, 0, -1)
  circle C1 centre (-53.5, -54) radius 1.71
extrude "Extrude34" add sketch "Close former inner mounting hole" along normal blind 12
work_plane "WorkPlane35" AlongDistance -36.1 ExtraOffset 0
sketch "Matched outer mounting row" plane through (-36.1, 0, 0) normal (1, 0, 0) x axis (0, 0, -1)
  circle C1 centre (-53.5, -70) radius 1.7
extrude "Extrude35" cut sketch "Matched outer mounting row" along normal blind 12.2
work_plane "WorkPlane33" AlongDistance 24 ExtraOffset 0
sketch "Close former inner mounting hole" plane through (24, 0, 0) normal (1, 0, 0) x axis (0, 0, -1)
  circle C1 centre (-53.5, -54) radius 1.71
extrude "Extrude33" add sketch "Close former inner mounting hole" along normal blind 12
work_plane "WorkPlane34" AlongDistance 23.9 ExtraOffset 0
sketch "Matched outer mounting row" plane through (23.9, 0, 0) normal (1, 0, 0) x axis (0, 0, -1)
  circle C1 centre (-53.5, -70) radius 1.7
extrude "Extrude34" cut sketch "Matched outer mounting row" along normal blind 12.2
work_plane "WorkPlane42" AlongDistance 37.9 ExtraOffset 0
sketch "Restore separate cup guide bore" plane through (0, 0, 37.9) normal (0, 0, 1) x axis (1, 0, 0)
  circle C1 centre (5, -55) radius 1.7
work_plane "WorkPlane43" AlongDistance 37.9 ExtraOffset 0
sketch "Restore separate cup guide bore (1)" plane through (0, 0, 37.9) normal (0, 0, 1) x axis (1, 0, 0)
  circle C1 centre (19, -55) radius 1.7
extrude "Extrude43" cut sketch "Restore separate cup guide bore (1)" along normal blind 21.2
work_plane "WorkPlane44" AlongDistance -24.1 ExtraOffset 0
sketch "Preserve cam envelope" plane through (-24.1, 0, 0) normal (1, 0, 0) x axis (0, 0, -1)
  circle C1 centre (-65, 0) radius 51
work_plane "WorkPlane36" AlongDistance -55 ExtraOffset 0
sketch "Close inaccessible rail head pocket" plane through (0, -55, 0) normal (0, 1, 0) x axis (1, 0, 0)
  circle C1 centre (-30, -45) radius 5.31
extrude "Extrude36" add sketch "Close inaccessible rail head pocket" along normal blind 12
work_plane "WorkPlane37" AlongDistance 43 ExtraOffset 0
sketch "Close inaccessible rail head pocket (1)" plane through (0, 43, 0) normal (0, 1, 0) x axis (1, 0, 0)
  circle C1 centre (-30, -45) radius 5.31
extrude "Extrude37" add sketch "Close inaccessible rail head pocket (1)" along normal blind 12
work_plane "WorkPlane38" AlongDistance -75 ExtraOffset 0
sketch "Close obsolete side rail bore" plane through (0, -75, 0) normal (0, 1, 0) x axis (1, 0, 0)
  circle C1 centre (-30, -45) radius 2.71
extrude "Extrude38" add sketch "Close obsolete side rail bore" along normal blind 20
work_plane "WorkPlane39" AlongDistance 55 ExtraOffset 0
sketch "Close obsolete side rail bore (1)" plane through (0, 55, 0) normal (0, 1, 0) x axis (1, 0, 0)
  circle C1 centre (-30, -45) radius 2.71
extrude "Extrude39" add sketch "Close obsolete side rail bore (1)" along normal blind 20
work_plane "WorkPlane40" AlongDistance -36 ExtraOffset 0
sketch "Top-access 2020 mounting flange" plane through (-36, 0, 0) normal (1, 0, 0) x axis (0, 0, -1)
  line L1 (-55, -70) -> (-55, -95)
  line L2 (-63, -70) -> (-55, -70)
  line L3 (-63, -95) -> (-63, -70)
  line L4 (-55, -95) -> (-63, -95)
extrude "Extrude40" add sketch "Top-access 2020 mounting flange" along normal blind 12
work_plane "WorkPlane41" AlongDistance -36 ExtraOffset 0
sketch "Mount root triangular reinforcement" plane through (-36, 0, 0) normal (1, 0, 0) x axis (0, 0, -1)
  line L1 (-56, -63) -> (-56, -70)
  line L2 (-63, -70) -> (-56, -63)
  line L3 (-56, -70) -> (-63, -70)
extrude "Extrude41" add sketch "Mount root triangular reinforcement" along normal blind 12
work_plane "WorkPlane42" AlongDistance 54.9 ExtraOffset 0
sketch "Vertical M5 rail mounting bore" plane through (0, 0, 54.9) normal (0, 0, 1) x axis (1, 0, 0)
  circle C1 centre (-30, -85) radius 2.7
extrude "Extrude42" cut sketch "Vertical M5 rail mounting bore" along normal blind 8.2
work_plane "WorkPlane43" AlongDistance -36 ExtraOffset 0
sketch "Top-access 2020 mounting flange (1)" plane through (-36, 0, 0) normal (1, 0, 0) x axis (0, 0, -1)
  line L1 (-55, 95) -> (-55, 70)
  line L2 (-63, 95) -> (-55, 95)
  line L3 (-63, 70) -> (-63, 95)
  line L4 (-55, 70) -> (-63, 70)
extrude "Extrude43" add sketch "Top-access 2020 mounting flange (1)" along normal blind 12
work_plane "WorkPlane44" AlongDistance -36 ExtraOffset 0
sketch "Mount root triangular reinforcement (1)" plane through (-36, 0, 0) normal (1, 0, 0) x axis (0, 0, -1)
  line L1 (-56, 70) -> (-56, 63)
  line L2 (-63, 70) -> (-56, 70)
  line L3 (-56, 63) -> (-63, 70)
extrude "Extrude44" add sketch "Mount root triangular reinforcement (1)" along normal blind 12
work_plane "WorkPlane45" AlongDistance 54.9 ExtraOffset 0
sketch "Vertical M5 rail mounting bore (1)" plane through (0, 0, 54.9) normal (0, 0, 1) x axis (1, 0, 0)
  circle C1 centre (-30, 85) radius 2.7
extrude "Extrude45" cut sketch "Vertical M5 rail mounting bore (1)" along normal blind 8.2
work_plane "WorkPlane46" AlongDistance -36 ExtraOffset 0
sketch "Close old M5 pivot clearance" plane through (-36, 0, 0) normal (1, 0, 0) x axis (0, 0, -1)
  circle C1 centre (-12, -35) radius 2.71
extrude "Extrude46" add sketch "Close old M5 pivot clearance" along normal blind 12
work_plane "WorkPlane47" AlongDistance -36.1 ExtraOffset 0
sketch "M3 follower pivot clearance" plane through (-36.1, 0, 0) normal (1, 0, 0) x axis (0, 0, -1)
  circle C1 centre (-12, -35) radius 1.7
extrude "Extrude47" cut sketch "M3 follower pivot clearance" along normal blind 12.2
work_plane "WorkPlane35" AlongDistance -55 ExtraOffset 0
sketch "Close inaccessible rail head pocket" plane through (0, -55, 0) normal (0, 1, 0) x axis (1, 0, 0)
  circle C1 centre (30, -45) radius 5.31
extrude "Extrude35" add sketch "Close inaccessible rail head pocket" along normal blind 12
work_plane "WorkPlane36" AlongDistance 43 ExtraOffset 0
sketch "Close inaccessible rail head pocket (1)" plane through (0, 43, 0) normal (0, 1, 0) x axis (1, 0, 0)
  circle C1 centre (30, -45) radius 5.31
extrude "Extrude36" add sketch "Close inaccessible rail head pocket (1)" along normal blind 12
work_plane "WorkPlane37" AlongDistance -75 ExtraOffset 0
sketch "Close obsolete side rail bore" plane through (0, -75, 0) normal (0, 1, 0) x axis (1, 0, 0)
  circle C1 centre (30, -45) radius 2.71
extrude "Extrude37" add sketch "Close obsolete side rail bore" along normal blind 20
work_plane "WorkPlane38" AlongDistance 55 ExtraOffset 0
sketch "Close obsolete side rail bore (1)" plane through (0, 55, 0) normal (0, 1, 0) x axis (1, 0, 0)
  circle C1 centre (30, -45) radius 2.71
extrude "Extrude38" add sketch "Close obsolete side rail bore (1)" along normal blind 20
work_plane "WorkPlane39" AlongDistance 24 ExtraOffset 0
sketch "Top-access 2020 mounting flange" plane through (24, 0, 0) normal (1, 0, 0) x axis (0, 0, -1)
  line L1 (-55, -70) -> (-55, -95)
  line L2 (-63, -70) -> (-55, -70)
  line L3 (-63, -95) -> (-63, -70)
  line L4 (-55, -95) -> (-63, -95)
extrude "Extrude39" add sketch "Top-access 2020 mounting flange" along normal blind 12
work_plane "WorkPlane40" AlongDistance 24 ExtraOffset 0
sketch "Mount root triangular reinforcement" plane through (24, 0, 0) normal (1, 0, 0) x axis (0, 0, -1)
  line L1 (-56, -63) -> (-56, -70)
  line L2 (-63, -70) -> (-56, -63)
  line L3 (-56, -70) -> (-63, -70)
extrude "Extrude40" add sketch "Mount root triangular reinforcement" along normal blind 12
work_plane "WorkPlane41" AlongDistance 54.9 ExtraOffset 0
sketch "Vertical M5 rail mounting bore" plane through (0, 0, 54.9) normal (0, 0, 1) x axis (1, 0, 0)
  circle C1 centre (30, -85) radius 2.7
extrude "Extrude41" cut sketch "Vertical M5 rail mounting bore" along normal blind 8.2
work_plane "WorkPlane42" AlongDistance 24 ExtraOffset 0
sketch "Top-access 2020 mounting flange (1)" plane through (24, 0, 0) normal (1, 0, 0) x axis (0, 0, -1)
  line L1 (-55, 95) -> (-55, 70)
  line L2 (-63, 95) -> (-55, 95)
  line L3 (-63, 70) -> (-63, 95)
  line L4 (-55, 70) -> (-63, 70)
extrude "Extrude42" add sketch "Top-access 2020 mounting flange (1)" along normal blind 12
work_plane "WorkPlane43" AlongDistance 24 ExtraOffset 0
sketch "Mount root triangular reinforcement (1)" plane through (24, 0, 0) normal (1, 0, 0) x axis (0, 0, -1)
  line L1 (-56, 70) -> (-56, 63)
  line L2 (-63, 70) -> (-56, 70)
  line L3 (-56, 63) -> (-63, 70)
extrude "Extrude43" add sketch "Mount root triangular reinforcement (1)" along normal blind 12
work_plane "WorkPlane44" AlongDistance 54.9 ExtraOffset 0
sketch "Vertical M5 rail mounting bore (1)" plane through (0, 0, 54.9) normal (0, 0, 1) x axis (1, 0, 0)
  circle C1 centre (30, 85) radius 2.7
extrude "Extrude44" cut sketch "Vertical M5 rail mounting bore (1)" along normal blind 8.2
work_plane "WorkPlane45" AlongDistance 24 ExtraOffset 0
sketch "Close old M5 pivot clearance" plane through (24, 0, 0) normal (1, 0, 0) x axis (0, 0, -1)
  circle C1 centre (-12, -35) radius 2.71
extrude "Extrude45" add sketch "Close old M5 pivot clearance" along normal blind 12
work_plane "WorkPlane46" AlongDistance 23.9 ExtraOffset 0
sketch "M3 follower pivot clearance" plane through (23.9, 0, 0) normal (1, 0, 0) x axis (0, 0, -1)
  circle C1 centre (-12, -35) radius 1.7
extrude "Extrude46" cut sketch "M3 follower pivot clearance" along normal blind 12.2
work_plane "WorkPlane47" AlongDistance 23.9 ExtraOffset 0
